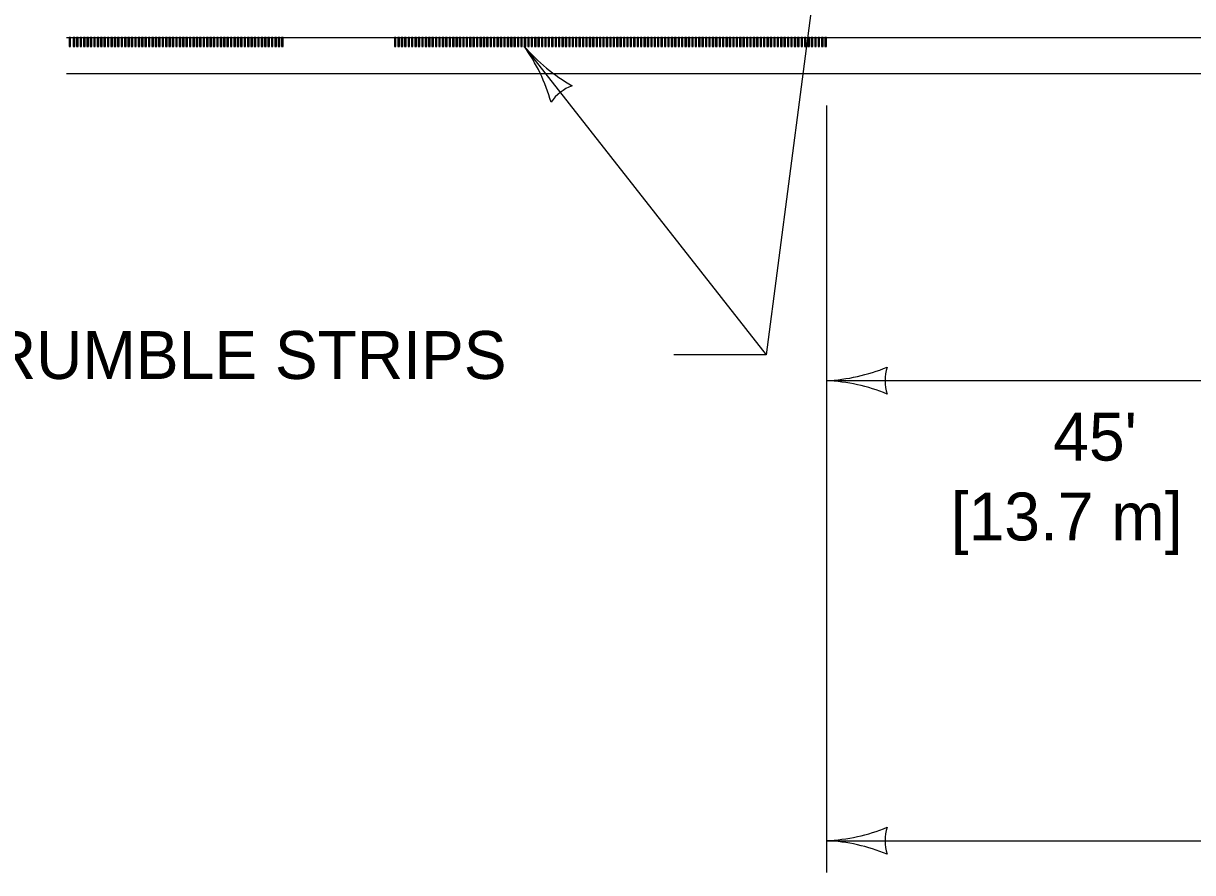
# Model space of a CAD drawing. Extents: x 49991.4 to 50021, y 49987.6 to 50011.4.
# Drawn here: x 50005.072 to 50006.534, y 49991.629 to 49992.692 of the extents above; entities that cross this region are included whole.
import ezdxf

# ---------------------------------------------------------------- set-up
doc = ezdxf.new("R2010")
doc.units = 0
for name, color, linetype in [('Level 1', 7, 'Continuous'), ('Level 2', 7, 'Continuous'), ('Level 3', 7, 'Continuous')]:
    doc.layers.add(name, color=color, linetype=linetype)

msp = doc.modelspace()

# ---------------------------------------------------------------- linework, layer by layer
at = {"layer": 'Level 1'}
for p, q in [((50005.1253, 49992.6746), (50011.5103, 49992.6746)), ((50005.1253, 49992.6296), (50006.7645, 49992.6296))]:
    msp.add_line(p, q, dxfattribs=at)
for points in [[(50005.1305, 49992.6746), (50005.1287, 49992.6746), (50005.1287, 49992.6634), (50005.1305, 49992.6634)], [(50005.1357, 49992.6746), (50005.1339, 49992.6746), (50005.1339, 49992.6634), (50005.1357, 49992.6634)], [(50005.14, 49992.6746), (50005.1381, 49992.6746), (50005.1381, 49992.6634), (50005.14, 49992.6634)], [(50005.1443, 49992.6746), (50005.1424, 49992.6746), (50005.1424, 49992.6634), (50005.1443, 49992.6634)], [(50005.1486, 49992.6746), (50005.1467, 49992.6746), (50005.1467, 49992.6634), (50005.1486, 49992.6634)], [(50005.1529, 49992.6746), (50005.1509, 49992.6746), (50005.1509, 49992.6634), (50005.1529, 49992.6634)], [(50005.1571, 49992.6746), (50005.1552, 49992.6746), (50005.1552, 49992.6634), (50005.1571, 49992.6634)], [(50005.1614, 49992.6746), (50005.1595, 49992.6746), (50005.1595, 49992.6634), (50005.1614, 49992.6634)], [(50005.1657, 49992.6746), (50005.1638, 49992.6746), (50005.1638, 49992.6634), (50005.1657, 49992.6634)], [(50005.1699, 49992.6746), (50005.1681, 49992.6746), (50005.1681, 49992.6634), (50005.1699, 49992.6634)], [(50005.1742, 49992.6746), (50005.1723, 49992.6746), (50005.1723, 49992.6634), (50005.1742, 49992.6634)], [(50005.1785, 49992.6746), (50005.1766, 49992.6746), (50005.1766, 49992.6634), (50005.1785, 49992.6634)], [(50005.1828, 49992.6746), (50005.1809, 49992.6746), (50005.1809, 49992.6634), (50005.1828, 49992.6634)], [(50005.1871, 49992.6746), (50005.1851, 49992.6746), (50005.1851, 49992.6634), (50005.1871, 49992.6634)], [(50005.1913, 49992.6746), (50005.1894, 49992.6746), (50005.1894, 49992.6634), (50005.1913, 49992.6634)], [(50005.1956, 49992.6746), (50005.1937, 49992.6746), (50005.1937, 49992.6634), (50005.1956, 49992.6634)], [(50005.1999, 49992.6746), (50005.198, 49992.6746), (50005.198, 49992.6634), (50005.1999, 49992.6634)], [(50005.2041, 49992.6746), (50005.2023, 49992.6746), (50005.2023, 49992.6634), (50005.2041, 49992.6634)], [(50005.2084, 49992.6746), (50005.2065, 49992.6746), (50005.2065, 49992.6634), (50005.2084, 49992.6634)], [(50005.2127, 49992.6746), (50005.2108, 49992.6746), (50005.2108, 49992.6634), (50005.2127, 49992.6634)], [(50005.217, 49992.6746), (50005.2151, 49992.6746), (50005.2151, 49992.6634), (50005.217, 49992.6634)], [(50005.2213, 49992.6746), (50005.2193, 49992.6746), (50005.2193, 49992.6634), (50005.2213, 49992.6634)], [(50005.2255, 49992.6746), (50005.2236, 49992.6746), (50005.2236, 49992.6634), (50005.2255, 49992.6634)], [(50005.2298, 49992.6746), (50005.2279, 49992.6746), (50005.2279, 49992.6634), (50005.2298, 49992.6634)], [(50005.2341, 49992.6746), (50005.2322, 49992.6746), (50005.2322, 49992.6634), (50005.2341, 49992.6634)], [(50005.2383, 49992.6746), (50005.2365, 49992.6746), (50005.2365, 49992.6634), (50005.2383, 49992.6634)], [(50005.2426, 49992.6746), (50005.2407, 49992.6746), (50005.2407, 49992.6634), (50005.2426, 49992.6634)], [(50005.2469, 49992.6746), (50005.245, 49992.6746), (50005.245, 49992.6634), (50005.2469, 49992.6634)], [(50005.2512, 49992.6746), (50005.2493, 49992.6746), (50005.2493, 49992.6634), (50005.2512, 49992.6634)], [(50005.2555, 49992.6746), (50005.2535, 49992.6746), (50005.2535, 49992.6634), (50005.2555, 49992.6634)], [(50005.2597, 49992.6746), (50005.2578, 49992.6746), (50005.2578, 49992.6634), (50005.2597, 49992.6634)], [(50005.264, 49992.6746), (50005.2621, 49992.6746), (50005.2621, 49992.6634), (50005.264, 49992.6634)], [(50005.2683, 49992.6746), (50005.2664, 49992.6746), (50005.2664, 49992.6634), (50005.2683, 49992.6634)], [(50005.2725, 49992.6746), (50005.2707, 49992.6746), (50005.2707, 49992.6634), (50005.2725, 49992.6634)], [(50005.2768, 49992.6746), (50005.2749, 49992.6746), (50005.2749, 49992.6634), (50005.2768, 49992.6634)], [(50005.2811, 49992.6746), (50005.2792, 49992.6746), (50005.2792, 49992.6634), (50005.2811, 49992.6634)], [(50005.2854, 49992.6746), (50005.2835, 49992.6746), (50005.2835, 49992.6634), (50005.2854, 49992.6634)], [(50005.2897, 49992.6746), (50005.2877, 49992.6746), (50005.2877, 49992.6634), (50005.2897, 49992.6634)], [(50005.2939, 49992.6746), (50005.292, 49992.6746), (50005.292, 49992.6634), (50005.2939, 49992.6634)], [(50005.2982, 49992.6746), (50005.2963, 49992.6746), (50005.2963, 49992.6634), (50005.2982, 49992.6634)], [(50005.3025, 49992.6746), (50005.3006, 49992.6746), (50005.3006, 49992.6634), (50005.3025, 49992.6634)], [(50005.3067, 49992.6746), (50005.3049, 49992.6746), (50005.3049, 49992.6634), (50005.3067, 49992.6634)], [(50005.311, 49992.6746), (50005.3091, 49992.6746), (50005.3091, 49992.6634), (50005.311, 49992.6634)], [(50005.3153, 49992.6746), (50005.3134, 49992.6746), (50005.3134, 49992.6634), (50005.3153, 49992.6634)], [(50005.3196, 49992.6746), (50005.3177, 49992.6746), (50005.3177, 49992.6634), (50005.3196, 49992.6634)], [(50005.3239, 49992.6746), (50005.3219, 49992.6746), (50005.3219, 49992.6634), (50005.3239, 49992.6634)], [(50005.3281, 49992.6746), (50005.3262, 49992.6746), (50005.3262, 49992.6634), (50005.3281, 49992.6634)], [(50005.3324, 49992.6746), (50005.3305, 49992.6746), (50005.3305, 49992.6634), (50005.3324, 49992.6634)], [(50005.3367, 49992.6746), (50005.3348, 49992.6746), (50005.3348, 49992.6634), (50005.3367, 49992.6634)], [(50005.3409, 49992.6746), (50005.3391, 49992.6746), (50005.3391, 49992.6634), (50005.3409, 49992.6634)], [(50005.3452, 49992.6746), (50005.3433, 49992.6746), (50005.3433, 49992.6634), (50005.3452, 49992.6634)], [(50005.3495, 49992.6746), (50005.3476, 49992.6746), (50005.3476, 49992.6634), (50005.3495, 49992.6634)], [(50005.3538, 49992.6746), (50005.3519, 49992.6746), (50005.3519, 49992.6634), (50005.3538, 49992.6634)], [(50005.3581, 49992.6746), (50005.3561, 49992.6746), (50005.3561, 49992.6634), (50005.3581, 49992.6634)], [(50005.3623, 49992.6746), (50005.3604, 49992.6746), (50005.3604, 49992.6634), (50005.3623, 49992.6634)], [(50005.3666, 49992.6746), (50005.3647, 49992.6746), (50005.3647, 49992.6634), (50005.3666, 49992.6634)], [(50005.3709, 49992.6746), (50005.369, 49992.6746), (50005.369, 49992.6634), (50005.3709, 49992.6634)], [(50005.3751, 49992.6746), (50005.3733, 49992.6746), (50005.3733, 49992.6634), (50005.3751, 49992.6634)], [(50005.3794, 49992.6746), (50005.3775, 49992.6746), (50005.3775, 49992.6634), (50005.3794, 49992.6634)], [(50005.3837, 49992.6746), (50005.3818, 49992.6746), (50005.3818, 49992.6634), (50005.3837, 49992.6634)], [(50005.388, 49992.6746), (50005.3861, 49992.6746), (50005.3861, 49992.6634), (50005.388, 49992.6634)], [(50005.3923, 49992.6746), (50005.3903, 49992.6746), (50005.3903, 49992.6634), (50005.3923, 49992.6634)], [(50005.3965, 49992.6746), (50005.3946, 49992.6746), (50005.3946, 49992.6634), (50005.3965, 49992.6634)], [(50005.5376, 49992.6746), (50005.5357, 49992.6746), (50005.5357, 49992.6634), (50005.5376, 49992.6634)], [(50005.5419, 49992.6746), (50005.5399, 49992.6746), (50005.5399, 49992.6634), (50005.5419, 49992.6634)], [(50005.5461, 49992.6746), (50005.5442, 49992.6746), (50005.5442, 49992.6634), (50005.5461, 49992.6634)], [(50005.5504, 49992.6746), (50005.5485, 49992.6746), (50005.5485, 49992.6634), (50005.5504, 49992.6634)], [(50005.5547, 49992.6746), (50005.5528, 49992.6746), (50005.5528, 49992.6634), (50005.5547, 49992.6634)], [(50005.5589, 49992.6746), (50005.5571, 49992.6746), (50005.5571, 49992.6634), (50005.5589, 49992.6634)], [(50005.5632, 49992.6746), (50005.5613, 49992.6746), (50005.5613, 49992.6634), (50005.5632, 49992.6634)], [(50005.5675, 49992.6746), (50005.5656, 49992.6746), (50005.5656, 49992.6634), (50005.5675, 49992.6634)], [(50005.5718, 49992.6746), (50005.5699, 49992.6746), (50005.5699, 49992.6634), (50005.5718, 49992.6634)], [(50005.5761, 49992.6746), (50005.5741, 49992.6746), (50005.5741, 49992.6634), (50005.5761, 49992.6634)], [(50005.5803, 49992.6746), (50005.5784, 49992.6746), (50005.5784, 49992.6634), (50005.5803, 49992.6634)], [(50005.5846, 49992.6746), (50005.5827, 49992.6746), (50005.5827, 49992.6634), (50005.5846, 49992.6634)], [(50005.5889, 49992.6746), (50005.587, 49992.6746), (50005.587, 49992.6634), (50005.5889, 49992.6634)], [(50005.5931, 49992.6746), (50005.5913, 49992.6746), (50005.5913, 49992.6634), (50005.5931, 49992.6634)], [(50005.5974, 49992.6746), (50005.5955, 49992.6746), (50005.5955, 49992.6634), (50005.5974, 49992.6634)], [(50005.6017, 49992.6746), (50005.5998, 49992.6746), (50005.5998, 49992.6634), (50005.6017, 49992.6634)], [(50005.606, 49992.6746), (50005.6041, 49992.6746), (50005.6041, 49992.6634), (50005.606, 49992.6634)], [(50005.6103, 49992.6746), (50005.6083, 49992.6746), (50005.6083, 49992.6634), (50005.6103, 49992.6634)], [(50005.6145, 49992.6746), (50005.6126, 49992.6746), (50005.6126, 49992.6634), (50005.6145, 49992.6634)], [(50005.6188, 49992.6746), (50005.6169, 49992.6746), (50005.6169, 49992.6634), (50005.6188, 49992.6634)], [(50005.6231, 49992.6746), (50005.6212, 49992.6746), (50005.6212, 49992.6634), (50005.6231, 49992.6634)], [(50005.6273, 49992.6746), (50005.6255, 49992.6746), (50005.6255, 49992.6634), (50005.6273, 49992.6634)], [(50005.6316, 49992.6746), (50005.6297, 49992.6746), (50005.6297, 49992.6634), (50005.6316, 49992.6634)], [(50005.6359, 49992.6746), (50005.634, 49992.6746), (50005.634, 49992.6634), (50005.6359, 49992.6634)], [(50005.6402, 49992.6746), (50005.6383, 49992.6746), (50005.6383, 49992.6634), (50005.6402, 49992.6634)], [(50005.6445, 49992.6746), (50005.6425, 49992.6746), (50005.6425, 49992.6634), (50005.6445, 49992.6634)], [(50005.6487, 49992.6746), (50005.6468, 49992.6746), (50005.6468, 49992.6634), (50005.6487, 49992.6634)], [(50005.653, 49992.6746), (50005.6511, 49992.6746), (50005.6511, 49992.6634), (50005.653, 49992.6634)], [(50005.6573, 49992.6746), (50005.6554, 49992.6746), (50005.6554, 49992.6634), (50005.6573, 49992.6634)], [(50005.6615, 49992.6746), (50005.6597, 49992.6746), (50005.6597, 49992.6634), (50005.6615, 49992.6634)], [(50005.6658, 49992.6746), (50005.6639, 49992.6746), (50005.6639, 49992.6634), (50005.6658, 49992.6634)], [(50005.6701, 49992.6746), (50005.6682, 49992.6746), (50005.6682, 49992.6634), (50005.6701, 49992.6634)], [(50005.6744, 49992.6746), (50005.6725, 49992.6746), (50005.6725, 49992.6634), (50005.6744, 49992.6634)], [(50005.6787, 49992.6746), (50005.6767, 49992.6746), (50005.6767, 49992.6634), (50005.6787, 49992.6634)], [(50005.6829, 49992.6746), (50005.681, 49992.6746), (50005.681, 49992.6634), (50005.6829, 49992.6634)], [(50005.6872, 49992.6746), (50005.6853, 49992.6746), (50005.6853, 49992.6634), (50005.6872, 49992.6634)], [(50005.6915, 49992.6746), (50005.6896, 49992.6746), (50005.6896, 49992.6634), (50005.6915, 49992.6634)], [(50005.6957, 49992.6746), (50005.6939, 49992.6746), (50005.6939, 49992.6634), (50005.6957, 49992.6634)], [(50005.7, 49992.6746), (50005.6981, 49992.6746), (50005.6981, 49992.6634), (50005.7, 49992.6634)], [(50005.7043, 49992.6746), (50005.7024, 49992.6746), (50005.7024, 49992.6634), (50005.7043, 49992.6634)], [(50005.7086, 49992.6746), (50005.7067, 49992.6746), (50005.7067, 49992.6634), (50005.7086, 49992.6634)], [(50005.7129, 49992.6746), (50005.7109, 49992.6746), (50005.7109, 49992.6634), (50005.7129, 49992.6634)], [(50005.7171, 49992.6746), (50005.7152, 49992.6746), (50005.7152, 49992.6634), (50005.7171, 49992.6634)], [(50005.7214, 49992.6746), (50005.7195, 49992.6746), (50005.7195, 49992.6634), (50005.7214, 49992.6634)], [(50005.7257, 49992.6746), (50005.7238, 49992.6746), (50005.7238, 49992.6634), (50005.7257, 49992.6634)], [(50005.7299, 49992.6746), (50005.7281, 49992.6746), (50005.7281, 49992.6634), (50005.7299, 49992.6634)], [(50005.7342, 49992.6746), (50005.7323, 49992.6746), (50005.7323, 49992.6634), (50005.7342, 49992.6634)], [(50005.7385, 49992.6746), (50005.7366, 49992.6746), (50005.7366, 49992.6634), (50005.7385, 49992.6634)], [(50005.7428, 49992.6746), (50005.7409, 49992.6746), (50005.7409, 49992.6634), (50005.7428, 49992.6634)], [(50005.7471, 49992.6746), (50005.7451, 49992.6746), (50005.7451, 49992.6634), (50005.7471, 49992.6634)], [(50005.7513, 49992.6746), (50005.7494, 49992.6746), (50005.7494, 49992.6634), (50005.7513, 49992.6634)], [(50005.7556, 49992.6746), (50005.7537, 49992.6746), (50005.7537, 49992.6634), (50005.7556, 49992.6634)], [(50005.7599, 49992.6746), (50005.758, 49992.6746), (50005.758, 49992.6634), (50005.7599, 49992.6634)], [(50005.7641, 49992.6746), (50005.7623, 49992.6746), (50005.7623, 49992.6634), (50005.7641, 49992.6634)], [(50005.7684, 49992.6746), (50005.7665, 49992.6746), (50005.7665, 49992.6634), (50005.7684, 49992.6634)], [(50005.7727, 49992.6746), (50005.7708, 49992.6746), (50005.7708, 49992.6634), (50005.7727, 49992.6634)], [(50005.777, 49992.6746), (50005.7751, 49992.6746), (50005.7751, 49992.6634), (50005.777, 49992.6634)], [(50005.7813, 49992.6746), (50005.7793, 49992.6746), (50005.7793, 49992.6634), (50005.7813, 49992.6634)], [(50005.7855, 49992.6746), (50005.7836, 49992.6746), (50005.7836, 49992.6634), (50005.7855, 49992.6634)], [(50005.7898, 49992.6746), (50005.7879, 49992.6746), (50005.7879, 49992.6634), (50005.7898, 49992.6634)], [(50005.7941, 49992.6746), (50005.7922, 49992.6746), (50005.7922, 49992.6634), (50005.7941, 49992.6634)], [(50005.7983, 49992.6746), (50005.7965, 49992.6746), (50005.7965, 49992.6634), (50005.7983, 49992.6634)], [(50005.8026, 49992.6746), (50005.8007, 49992.6746), (50005.8007, 49992.6634), (50005.8026, 49992.6634)], [(50005.8069, 49992.6746), (50005.805, 49992.6746), (50005.805, 49992.6634), (50005.8069, 49992.6634)], [(50005.8112, 49992.6746), (50005.8093, 49992.6746), (50005.8093, 49992.6634), (50005.8112, 49992.6634)], [(50005.8155, 49992.6746), (50005.8135, 49992.6746), (50005.8135, 49992.6634), (50005.8155, 49992.6634)], [(50005.8197, 49992.6746), (50005.8178, 49992.6746), (50005.8178, 49992.6634), (50005.8197, 49992.6634)], [(50005.824, 49992.6746), (50005.8221, 49992.6746), (50005.8221, 49992.6634), (50005.824, 49992.6634)], [(50005.8283, 49992.6746), (50005.8264, 49992.6746), (50005.8264, 49992.6634), (50005.8283, 49992.6634)], [(50005.8325, 49992.6746), (50005.8307, 49992.6746), (50005.8307, 49992.6634), (50005.8325, 49992.6634)], [(50005.8368, 49992.6746), (50005.8349, 49992.6746), (50005.8349, 49992.6634), (50005.8368, 49992.6634)], [(50005.8411, 49992.6746), (50005.8392, 49992.6746), (50005.8392, 49992.6634), (50005.8411, 49992.6634)], [(50005.8454, 49992.6746), (50005.8435, 49992.6746), (50005.8435, 49992.6634), (50005.8454, 49992.6634)], [(50005.8497, 49992.6746), (50005.8477, 49992.6746), (50005.8477, 49992.6634), (50005.8497, 49992.6634)], [(50005.8539, 49992.6746), (50005.852, 49992.6746), (50005.852, 49992.6634), (50005.8539, 49992.6634)], [(50005.8582, 49992.6746), (50005.8563, 49992.6746), (50005.8563, 49992.6634), (50005.8582, 49992.6634)], [(50005.8625, 49992.6746), (50005.8606, 49992.6746), (50005.8606, 49992.6634), (50005.8625, 49992.6634)], [(50005.8667, 49992.6746), (50005.8649, 49992.6746), (50005.8649, 49992.6634), (50005.8667, 49992.6634)], [(50005.871, 49992.6746), (50005.8691, 49992.6746), (50005.8691, 49992.6634), (50005.871, 49992.6634)], [(50005.8753, 49992.6746), (50005.8734, 49992.6746), (50005.8734, 49992.6634), (50005.8753, 49992.6634)], [(50005.8796, 49992.6746), (50005.8777, 49992.6746), (50005.8777, 49992.6634), (50005.8796, 49992.6634)], [(50005.8839, 49992.6746), (50005.8819, 49992.6746), (50005.8819, 49992.6634), (50005.8839, 49992.6634)], [(50005.8881, 49992.6746), (50005.8862, 49992.6746), (50005.8862, 49992.6634), (50005.8881, 49992.6634)], [(50005.8924, 49992.6746), (50005.8905, 49992.6746), (50005.8905, 49992.6634), (50005.8924, 49992.6634)], [(50005.8967, 49992.6746), (50005.8948, 49992.6746), (50005.8948, 49992.6634), (50005.8967, 49992.6634)], [(50005.9009, 49992.6746), (50005.8991, 49992.6746), (50005.8991, 49992.6634), (50005.9009, 49992.6634)], [(50005.9052, 49992.6746), (50005.9033, 49992.6746), (50005.9033, 49992.6634), (50005.9052, 49992.6634)], [(50005.9095, 49992.6746), (50005.9076, 49992.6746), (50005.9076, 49992.6634), (50005.9095, 49992.6634)], [(50005.9138, 49992.6746), (50005.9119, 49992.6746), (50005.9119, 49992.6634), (50005.9138, 49992.6634)], [(50005.9181, 49992.6746), (50005.9161, 49992.6746), (50005.9161, 49992.6634), (50005.9181, 49992.6634)], [(50005.9223, 49992.6746), (50005.9204, 49992.6746), (50005.9204, 49992.6634), (50005.9223, 49992.6634)], [(50005.9266, 49992.6746), (50005.9247, 49992.6746), (50005.9247, 49992.6634), (50005.9266, 49992.6634)], [(50005.9309, 49992.6746), (50005.9289, 49992.6746), (50005.9289, 49992.6634), (50005.9309, 49992.6634)], [(50005.9351, 49992.6746), (50005.9332, 49992.6746), (50005.9332, 49992.6634), (50005.9351, 49992.6634)], [(50005.9394, 49992.6746), (50005.9375, 49992.6746), (50005.9375, 49992.6634), (50005.9394, 49992.6634)], [(50005.9437, 49992.6746), (50005.9418, 49992.6746), (50005.9418, 49992.6634), (50005.9437, 49992.6634)], [(50005.9479, 49992.6746), (50005.9461, 49992.6746), (50005.9461, 49992.6634), (50005.9479, 49992.6634)], [(50005.9522, 49992.6746), (50005.9503, 49992.6746), (50005.9503, 49992.6634), (50005.9522, 49992.6634)], [(50005.9565, 49992.6746), (50005.9546, 49992.6746), (50005.9546, 49992.6634), (50005.9565, 49992.6634)], [(50005.9608, 49992.6746), (50005.9589, 49992.6746), (50005.9589, 49992.6634), (50005.9608, 49992.6634)], [(50005.9651, 49992.6746), (50005.9631, 49992.6746), (50005.9631, 49992.6634), (50005.9651, 49992.6634)], [(50005.9693, 49992.6746), (50005.9674, 49992.6746), (50005.9674, 49992.6634), (50005.9693, 49992.6634)], [(50005.9736, 49992.6746), (50005.9717, 49992.6746), (50005.9717, 49992.6634), (50005.9736, 49992.6634)], [(50005.9779, 49992.6746), (50005.976, 49992.6746), (50005.976, 49992.6634), (50005.9779, 49992.6634)], [(50005.9821, 49992.6746), (50005.9803, 49992.6746), (50005.9803, 49992.6634), (50005.9821, 49992.6634)], [(50005.9864, 49992.6746), (50005.9845, 49992.6746), (50005.9845, 49992.6634), (50005.9864, 49992.6634)], [(50005.9907, 49992.6746), (50005.9888, 49992.6746), (50005.9888, 49992.6634), (50005.9907, 49992.6634)], [(50005.995, 49992.6746), (50005.9931, 49992.6746), (50005.9931, 49992.6634), (50005.995, 49992.6634)], [(50005.9993, 49992.6746), (50005.9973, 49992.6746), (50005.9973, 49992.6634), (50005.9993, 49992.6634)], [(50006.0035, 49992.6746), (50006.0016, 49992.6746), (50006.0016, 49992.6634), (50006.0035, 49992.6634)], [(50006.0078, 49992.6746), (50006.0059, 49992.6746), (50006.0059, 49992.6634), (50006.0078, 49992.6634)], [(50006.0121, 49992.6746), (50006.0102, 49992.6746), (50006.0102, 49992.6634), (50006.0121, 49992.6634)], [(50006.0163, 49992.6746), (50006.0145, 49992.6746), (50006.0145, 49992.6634), (50006.0163, 49992.6634)], [(50006.0206, 49992.6746), (50006.0187, 49992.6746), (50006.0187, 49992.6634), (50006.0206, 49992.6634)], [(50006.0249, 49992.6746), (50006.023, 49992.6746), (50006.023, 49992.6634), (50006.0249, 49992.6634)], [(50006.0292, 49992.6746), (50006.0273, 49992.6746), (50006.0273, 49992.6634), (50006.0292, 49992.6634)], [(50006.0335, 49992.6746), (50006.0315, 49992.6746), (50006.0315, 49992.6634), (50006.0335, 49992.6634)], [(50006.0377, 49992.6746), (50006.0358, 49992.6746), (50006.0358, 49992.6634), (50006.0377, 49992.6634)], [(50006.042, 49992.6746), (50006.0401, 49992.6746), (50006.0401, 49992.6634), (50006.042, 49992.6634)], [(50006.0463, 49992.6746), (50006.0444, 49992.6746), (50006.0444, 49992.6634), (50006.0463, 49992.6634)], [(50006.0505, 49992.6746), (50006.0487, 49992.6746), (50006.0487, 49992.6634), (50006.0505, 49992.6634)], [(50006.0548, 49992.6746), (50006.0529, 49992.6746), (50006.0529, 49992.6634), (50006.0548, 49992.6634)], [(50006.0591, 49992.6746), (50006.0572, 49992.6746), (50006.0572, 49992.6634), (50006.0591, 49992.6634)], [(50006.0634, 49992.6746), (50006.0615, 49992.6746), (50006.0615, 49992.6634), (50006.0634, 49992.6634)], [(50006.0677, 49992.6746), (50006.0657, 49992.6746), (50006.0657, 49992.6634), (50006.0677, 49992.6634)], [(50006.0719, 49992.6746), (50006.07, 49992.6746), (50006.07, 49992.6634), (50006.0719, 49992.6634)], [(50006.0761, 49992.6746), (50006.0742, 49992.6746), (50006.0742, 49992.6634), (50006.0761, 49992.6634)]]:
    msp.add_lwpolyline(points, close=True, dxfattribs=at)
at = {"layer": 'Level 3'}
for p, q in [((50006.0881, 49992.9446), (50006.0007, 49992.2771)), ((50005.6981, 49992.6634), (50006.0007, 49992.2771)), ((50006.0761, 49992.5896), (50006.0761, 49991.6291)), ((50006.0007, 49992.2771), (50005.8852, 49992.2771)), ((50006.7644, 49992.2449), (50006.0761, 49992.2449)), ((50006.0761, 49991.6691), (50007.9826, 49991.6691))]:
    msp.add_line(p, q, dxfattribs=at)
for centre, radius, start, end in [((50005.5175, 49992.5338), 0.2223, 15.544, 35.7275), ((50005.874, 49992.8162), 0.233, 220.9153, 240.1652), ((50005.777, 49992.5627), 0.0548, 110.2268, 145.9492), ((50006.0646, 49992.4777), 0.233, 272.8273, 292.0772), ((50006.2043, 49992.2449), 0.0548, 162.1388, 197.8612), ((50006.0669, 49992.0228), 0.2223, 67.456, 87.6395), ((50006.0646, 49991.9018), 0.233, 272.8273, 292.0772), ((50006.2043, 49991.6691), 0.0548, 162.1388, 197.8612), ((50006.0669, 49991.4469), 0.2223, 67.456, 87.6395)]:
    msp.add_arc(centre, radius, start, end, dxfattribs=at)

# ---------------------------------------------------------------- texts
at = {"layer": 'Level 2'}
msp.add_text('INTERMITTENT RUMBLE STRIPS', height=0.06, rotation=359.9999, dxfattribs=at).set_placement((50004.4189, 49992.2471))
for s, p in [("45'", (50006.36, 49992.1449)), ('[13.7 m]', (50006.2318, 49992.0449))]:
    msp.add_text(s, height=0.06, dxfattribs=at).set_placement(p)

doc.saveas('drawing.dxf')
